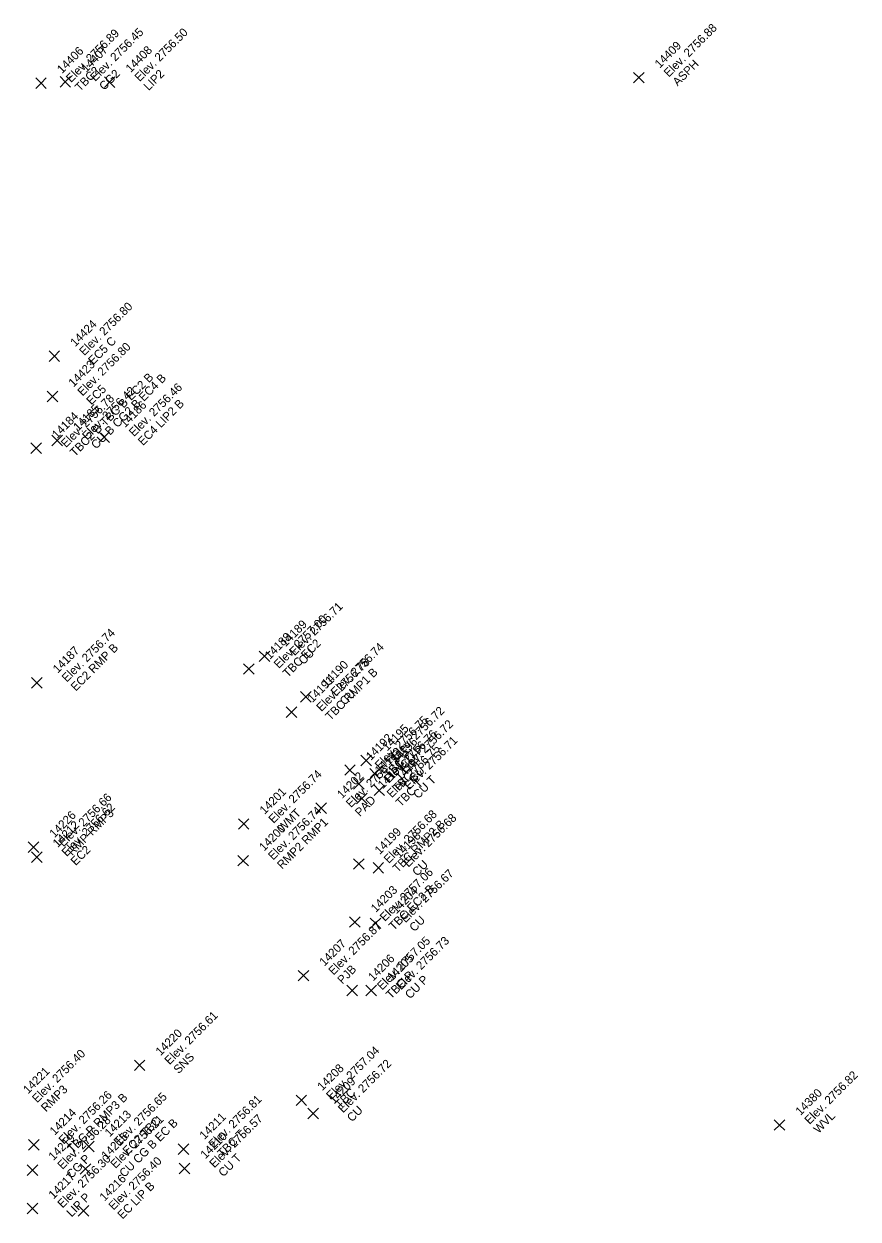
# Model space of a CAD drawing. Extents: x 2493999 to 2503109, y 700767 to 706646.
# Drawn here: x 2502335.47 to 2502359.11, y 703210.64 to 703244.51 of the extents above; entities that cross this region are included whole.
import ezdxf

# ---------------------------------------------------------------- set-up
doc = ezdxf.new("R2010")
doc.units = 0
doc.layers.add('ALG_CL_BLUE_Horiz', color=7, linetype='Continuous')
doc.layers.add('DES_SURFACE_Existing-Ground', color=7, linetype='Continuous')

msp = doc.modelspace()

# ---------------------------------------------------------------- linework, layer by layer
at = {"layer": 'ALG_CL_BLUE_Horiz'}
for points in [[(2502352.892, 703242.983), (2502352.742, 703243.133), (2502352.892, 703242.983), (2502352.742, 703242.833), (2502352.892, 703242.983), (2502353.042, 703242.833), (2502352.892, 703242.983), (2502353.042, 703243.133)], [(2502335.954, 703242.83), (2502335.804, 703242.98), (2502335.954, 703242.83), (2502335.804, 703242.68), (2502335.954, 703242.83), (2502336.104, 703242.68), (2502335.954, 703242.83), (2502336.104, 703242.98)], [(2502336.642, 703242.861), (2502336.492, 703243.011), (2502336.642, 703242.861), (2502336.492, 703242.711), (2502336.642, 703242.861), (2502336.792, 703242.711), (2502336.642, 703242.861), (2502336.792, 703243.011)], [(2502337.899, 703242.855), (2502337.749, 703243.005), (2502337.899, 703242.855), (2502337.749, 703242.705), (2502337.899, 703242.855), (2502338.049, 703242.705), (2502337.899, 703242.855), (2502338.049, 703243.005)], [(2502336.332, 703235.088), (2502336.182, 703235.238), (2502336.332, 703235.088), (2502336.182, 703234.938), (2502336.332, 703235.088), (2502336.482, 703234.938), (2502336.332, 703235.088), (2502336.482, 703235.238)], [(2502336.279, 703233.947), (2502336.129, 703234.097), (2502336.279, 703233.947), (2502336.129, 703233.797), (2502336.279, 703233.947), (2502336.429, 703233.797), (2502336.279, 703233.947), (2502336.429, 703234.097)], [(2502337.74, 703232.796), (2502337.59, 703232.946), (2502337.74, 703232.796), (2502337.59, 703232.646), (2502337.74, 703232.796), (2502337.89, 703232.646), (2502337.74, 703232.796), (2502337.89, 703232.946)], [(2502335.813, 703232.483), (2502335.663, 703232.633), (2502335.813, 703232.483), (2502335.663, 703232.333), (2502335.813, 703232.483), (2502335.963, 703232.333), (2502335.813, 703232.483), (2502335.963, 703232.633)], [(2502336.413, 703232.698), (2502336.263, 703232.848), (2502336.413, 703232.698), (2502336.263, 703232.548), (2502336.413, 703232.698), (2502336.563, 703232.548), (2502336.413, 703232.698), (2502336.563, 703232.848)], [(2502342.288, 703226.587), (2502342.138, 703226.737), (2502342.288, 703226.587), (2502342.138, 703226.437), (2502342.288, 703226.587), (2502342.438, 703226.437), (2502342.288, 703226.587), (2502342.438, 703226.737)], [(2502341.843, 703226.228), (2502341.693, 703226.378), (2502341.843, 703226.228), (2502341.693, 703226.078), (2502341.843, 703226.228), (2502341.993, 703226.078), (2502341.843, 703226.228), (2502341.993, 703226.378)], [(2502335.836, 703225.838), (2502335.686, 703225.988), (2502335.836, 703225.838), (2502335.686, 703225.688), (2502335.836, 703225.838), (2502335.986, 703225.688), (2502335.836, 703225.838), (2502335.986, 703225.988)], [(2502343.457, 703225.438), (2502343.307, 703225.588), (2502343.457, 703225.438), (2502343.307, 703225.288), (2502343.457, 703225.438), (2502343.607, 703225.288), (2502343.457, 703225.438), (2502343.607, 703225.588)], [(2502343.052, 703225.005), (2502342.902, 703225.155), (2502343.052, 703225.005), (2502342.902, 703224.855), (2502343.052, 703225.005), (2502343.202, 703224.855), (2502343.052, 703225.005), (2502343.202, 703225.155)], [(2502345.17, 703223.633), (2502345.02, 703223.783), (2502345.17, 703223.633), (2502345.02, 703223.483), (2502345.17, 703223.633), (2502345.32, 703223.483), (2502345.17, 703223.633), (2502345.32, 703223.783)], [(2502344.709, 703223.365), (2502344.559, 703223.515), (2502344.709, 703223.365), (2502344.559, 703223.215), (2502344.709, 703223.365), (2502344.859, 703223.215), (2502344.709, 703223.365), (2502344.859, 703223.515)], [(2502344.959, 703222.972), (2502344.809, 703223.122), (2502344.959, 703222.972), (2502344.809, 703222.822), (2502344.959, 703222.972), (2502345.109, 703222.822), (2502344.959, 703222.972), (2502345.109, 703223.122)], [(2502345.417, 703223.256), (2502345.267, 703223.406), (2502345.417, 703223.256), (2502345.267, 703223.106), (2502345.417, 703223.256), (2502345.567, 703223.106), (2502345.417, 703223.256), (2502345.567, 703223.406)], [(2502345.54, 703222.789), (2502345.39, 703222.939), (2502345.54, 703222.789), (2502345.39, 703222.639), (2502345.54, 703222.789), (2502345.69, 703222.639), (2502345.54, 703222.789), (2502345.69, 703222.939)], [(2502343.891, 703222.282), (2502343.741, 703222.432), (2502343.891, 703222.282), (2502343.741, 703222.132), (2502343.891, 703222.282), (2502344.041, 703222.132), (2502343.891, 703222.282), (2502344.041, 703222.432)], [(2502345.046, 703222.559), (2502344.896, 703222.709), (2502345.046, 703222.559), (2502344.896, 703222.409), (2502345.046, 703222.559), (2502345.196, 703222.409), (2502345.046, 703222.559), (2502345.196, 703222.709)], [(2502341.697, 703221.836), (2502341.547, 703221.986), (2502341.697, 703221.836), (2502341.547, 703221.686), (2502341.697, 703221.836), (2502341.847, 703221.686), (2502341.697, 703221.836), (2502341.847, 703221.986)], [(2502335.74, 703221.176), (2502335.59, 703221.326), (2502335.74, 703221.176), (2502335.59, 703221.026), (2502335.74, 703221.176), (2502335.89, 703221.026), (2502335.74, 703221.176), (2502335.89, 703221.326)], [(2502335.834, 703220.896), (2502335.684, 703221.046), (2502335.834, 703220.896), (2502335.684, 703220.746), (2502335.834, 703220.896), (2502335.984, 703220.746), (2502335.834, 703220.896), (2502335.984, 703221.046)], [(2502341.682, 703220.796), (2502341.532, 703220.946), (2502341.682, 703220.796), (2502341.532, 703220.646), (2502341.682, 703220.796), (2502341.832, 703220.646), (2502341.682, 703220.796), (2502341.832, 703220.946)], [(2502344.958, 703220.702), (2502344.808, 703220.852), (2502344.958, 703220.702), (2502344.808, 703220.552), (2502344.958, 703220.702), (2502345.108, 703220.552), (2502344.958, 703220.702), (2502345.108, 703220.852)], [(2502345.513, 703220.595), (2502345.363, 703220.745), (2502345.513, 703220.595), (2502345.363, 703220.445), (2502345.513, 703220.595), (2502345.663, 703220.445), (2502345.513, 703220.595), (2502345.663, 703220.745)], [(2502344.849, 703219.058), (2502344.699, 703219.208), (2502344.849, 703219.058), (2502344.699, 703218.908), (2502344.849, 703219.058), (2502344.999, 703218.908), (2502344.849, 703219.058), (2502344.999, 703219.208)], [(2502345.431, 703219.021), (2502345.281, 703219.171), (2502345.431, 703219.021), (2502345.281, 703218.871), (2502345.431, 703219.021), (2502345.581, 703218.871), (2502345.431, 703219.021), (2502345.581, 703219.171)], [(2502343.39, 703217.538), (2502343.24, 703217.688), (2502343.39, 703217.538), (2502343.24, 703217.388), (2502343.39, 703217.538), (2502343.54, 703217.388), (2502343.39, 703217.538), (2502343.54, 703217.688)], [(2502344.77, 703217.115), (2502344.62, 703217.265), (2502344.77, 703217.115), (2502344.62, 703216.965), (2502344.77, 703217.115), (2502344.92, 703216.965), (2502344.77, 703217.115), (2502344.92, 703217.265)], [(2502345.308, 703217.117), (2502345.158, 703217.267), (2502345.308, 703217.117), (2502345.158, 703216.967), (2502345.308, 703217.117), (2502345.458, 703216.967), (2502345.308, 703217.117), (2502345.458, 703217.267)], [(2502338.749, 703214.998), (2502338.599, 703215.148), (2502338.749, 703214.998), (2502338.599, 703214.848), (2502338.749, 703214.998), (2502338.899, 703214.848), (2502338.749, 703214.998), (2502338.899, 703215.148)], [(2502343.331, 703214.006), (2502343.181, 703214.156), (2502343.331, 703214.006), (2502343.181, 703213.856), (2502343.331, 703214.006), (2502343.481, 703213.856), (2502343.331, 703214.006), (2502343.481, 703214.156)], [(2502343.663, 703213.633), (2502343.513, 703213.783), (2502343.663, 703213.633), (2502343.513, 703213.483), (2502343.663, 703213.633), (2502343.813, 703213.483), (2502343.663, 703213.633), (2502343.813, 703213.783)], [(2502356.883, 703213.306), (2502356.733, 703213.456), (2502356.883, 703213.306), (2502356.733, 703213.156), (2502356.883, 703213.306), (2502357.033, 703213.156), (2502356.883, 703213.306), (2502357.033, 703213.456)], [(2502335.748, 703212.744), (2502335.598, 703212.894), (2502335.748, 703212.744), (2502335.598, 703212.594), (2502335.748, 703212.744), (2502335.898, 703212.594), (2502335.748, 703212.744), (2502335.898, 703212.894)], [(2502337.306, 703212.696), (2502337.156, 703212.846), (2502337.306, 703212.696), (2502337.156, 703212.546), (2502337.306, 703212.696), (2502337.456, 703212.546), (2502337.306, 703212.696), (2502337.456, 703212.846)], [(2502339.993, 703212.624), (2502339.843, 703212.774), (2502339.993, 703212.624), (2502339.843, 703212.474), (2502339.993, 703212.624), (2502340.143, 703212.474), (2502339.993, 703212.624), (2502340.143, 703212.774)], [(2502335.714, 703212.029), (2502335.564, 703212.179), (2502335.714, 703212.029), (2502335.564, 703211.879), (2502335.714, 703212.029), (2502335.864, 703211.879), (2502335.714, 703212.029), (2502335.864, 703212.179)], [(2502337.212, 703212.06), (2502337.062, 703212.21), (2502337.212, 703212.06), (2502337.062, 703211.91), (2502337.212, 703212.06), (2502337.362, 703211.91), (2502337.212, 703212.06), (2502337.362, 703212.21)], [(2502340.019, 703212.076), (2502339.869, 703212.226), (2502340.019, 703212.076), (2502339.869, 703211.926), (2502340.019, 703212.076), (2502340.169, 703211.926), (2502340.019, 703212.076), (2502340.169, 703212.226)], [(2502335.714, 703210.938), (2502335.564, 703211.088), (2502335.714, 703210.938), (2502335.564, 703210.788), (2502335.714, 703210.938), (2502335.864, 703210.788), (2502335.714, 703210.938), (2502335.864, 703211.088)], [(2502337.16, 703210.876), (2502337.01, 703211.026), (2502337.16, 703210.876), (2502337.01, 703210.726), (2502337.16, 703210.876), (2502337.31, 703210.726), (2502337.16, 703210.876), (2502337.31, 703211.026)]]:
    msp.add_lwpolyline(points, dxfattribs=at)

# ---------------------------------------------------------------- texts
at = {"layer": 'DES_SURFACE_Existing-Ground'}
for s, p in [('Elev. 2756.88', (2502353.741, 703242.983)), ('Elev. 2756.89', (2502336.803, 703242.83)), ('Elev. 2756.45', (2502337.491, 703242.861)), ('Elev. 2756.50', (2502338.748, 703242.855)), ('14406', (2502336.548, 703243.085)), ('14407', (2502337.236, 703243.116)), ('14408', (2502338.493, 703243.11)), ('14409', (2502353.486, 703243.238)), ('ASPH', (2502353.995, 703242.728)), ('TBC2', (2502337.057, 703242.575)), ('CG2', (2502337.745, 703242.606)), ('LIP2', (2502339.002, 703242.6)), ('Elev. 2756.80', (2502337.181, 703235.088)), ('14424', (2502336.926, 703235.343)), ('EC5 C', (2502337.435, 703234.833)), ('Elev. 2756.80', (2502337.128, 703233.947)), ('14423', (2502336.873, 703234.202)), ('TBC2 B TBC B EC2 B', (2502336.916, 703232.228)), ('EC5', (2502337.382, 703233.692)), ('CU B CG2 B EC4 B', (2502337.516, 703232.443)), ('Elev. 2756.46', (2502338.589, 703232.796)), ('Elev. 2756.78', (2502336.662, 703232.483)), ('Elev. 2756.42', (2502337.262, 703232.698)), ('14185', (2502337.007, 703232.953)), ('14186', (2502338.334, 703233.051)), ('EC4 LIP2 B', (2502338.843, 703232.541)), ('14184', (2502336.407, 703232.738)), ('Elev. 2756.71', (2502343.137, 703226.587)), ('Elev. 2757.00', (2502342.692, 703226.228)), ('14189', (2502342.882, 703226.842)), ('Elev. 2756.74', (2502336.685, 703225.838)), ('14188', (2502342.437, 703226.483)), ('14187', (2502336.43, 703226.093)), ('EC2 RMP B', (2502336.939, 703225.583)), ('TBC EC2', (2502342.946, 703225.973)), ('Elev. 2756.74', (2502344.306, 703225.438)), ('CU', (2502343.391, 703226.332)), ('Elev. 2756.78', (2502343.901, 703225.005)), ('14190', (2502344.051, 703225.693)), ('TBC RMP1 B', (2502344.155, 703224.75)), ('14191', (2502343.646, 703225.26)), ('CU', (2502344.56, 703225.183)), ('Elev. 2756.72', (2502346.019, 703223.633)), ('Elev. 2756.75', (2502345.558, 703223.365)), ('14195', (2502345.764, 703223.888)), ('Elev. 2756.76', (2502345.808, 703222.972)), ('Elev. 2756.72', (2502346.266, 703223.256)), ('14192', (2502345.303, 703223.62)), ('14196', (2502346.011, 703223.511)), ('Elev. 2756.71', (2502346.389, 703222.789)), ('Elev. 2756.73', (2502344.74, 703222.282)), ('14193', (2502345.553, 703223.227)), ('TBC P', (2502345.812, 703223.11)), ('Elev. 2756.75', (2502345.895, 703222.559)), ('14197', (2502346.134, 703223.044)), ('CU P', (2502346.273, 703223.378)), ('14194', (2502345.64, 703222.814)), ('CU', (2502346.52, 703223.001)), ('Elev. 2756.74', (2502342.546, 703221.836)), ('14202', (2502344.485, 703222.537)), ('TBC', (2502346.062, 703222.717)), ('TBC T', (2502346.149, 703222.304)), ('CU T', (2502346.643, 703222.534)), ('14201', (2502342.291, 703222.091)), ('Elev. 2756.66', (2502336.589, 703221.176)), ('Elev. 2756.62', (2502336.683, 703220.896)), ('PAD', (2502344.994, 703222.027)), ('14226', (2502336.334, 703221.431)), ('RMP RMP3', (2502336.843, 703220.921)), ('Elev. 2756.74', (2502342.531, 703220.796)), ('WMT', (2502342.8, 703221.581)), ('Elev. 2756.68', (2502345.807, 703220.702)), ('Elev. 2756.68', (2502346.362, 703220.595)), ('14212', (2502336.428, 703221.151)), ('14200', (2502342.276, 703221.051)), ('RMP2 RMP1', (2502342.785, 703220.541)), ('TBC RMP2 B', (2502346.061, 703220.447)), ('14199', (2502345.552, 703220.957)), ('14198', (2502346.107, 703220.85)), ('EC2', (2502336.937, 703220.641)), ('CU', (2502346.616, 703220.34)), ('Elev. 2757.06', (2502345.698, 703219.058)), ('Elev. 2756.67', (2502346.28, 703219.021)), ('14203', (2502345.443, 703219.313)), ('TBC EC2 B', (2502345.952, 703218.803)), ('14204', (2502346.025, 703219.276)), ('Elev. 2756.87', (2502344.239, 703217.538)), ('CU', (2502346.534, 703218.766)), ('14207', (2502343.984, 703217.793)), ('Elev. 2757.05', (2502345.619, 703217.115)), ('Elev. 2756.73', (2502346.157, 703217.117)), ('14206', (2502345.364, 703217.37)), ('14205', (2502345.902, 703217.372)), ('PJB', (2502344.493, 703217.283)), ('TBC P', (2502345.873, 703216.86)), ('CU P', (2502346.411, 703216.862)), ('Elev. 2756.61', (2502339.598, 703214.998)), ('14220', (2502339.343, 703215.253)), ('Elev. 2756.40', (2502335.844, 703213.917)), ('SNS', (2502339.852, 703214.743)), ('Elev. 2757.04', (2502344.18, 703214.006)), ('14208', (2502343.925, 703214.261)), ('Elev. 2756.72', (2502344.512, 703213.633)), ('14221', (2502335.589, 703214.172)), ('14209', (2502344.257, 703213.888)), ('Elev. 2756.82', (2502357.732, 703213.306)), ('RMP3', (2502336.098, 703213.662)), ('TBC', (2502344.434, 703213.751)), ('14380', (2502357.477, 703213.561)), ('Elev. 2756.26', (2502336.597, 703212.744)), ('TBC P RMP3 B', (2502336.851, 703212.489)), ('Elev. 2756.65', (2502338.155, 703212.696)), ('Elev. 2756.81', (2502340.842, 703212.624)), ('14214', (2502336.342, 703212.999)), ('14213', (2502337.9, 703212.951)), ('14211', (2502340.587, 703212.879)), ('Elev. 2756.57', (2502340.868, 703212.076)), ('CU', (2502344.766, 703213.378)), ('WVL', (2502357.986, 703213.051)), ('Elev. 2756.28', (2502336.563, 703212.029)), ('Elev. 2756.21', (2502338.061, 703212.06)), ('CU CG B EC B', (2502338.315, 703211.805)), ('EC2 TBC', (2502338.409, 703212.441)), ('14219', (2502336.308, 703212.284)), ('14215', (2502337.806, 703212.315)), ('14210', (2502340.613, 703212.331)), ('TBC T', (2502341.096, 703212.369)), ('Elev. 2756.30', (2502336.563, 703210.938)), ('CG P', (2502336.817, 703211.774)), ('Elev. 2756.40', (2502338.009, 703210.876)), ('CU T', (2502341.122, 703211.821)), ('14217', (2502336.308, 703211.193)), ('14216', (2502337.754, 703211.131)), ('EC LIP B', (2502338.263, 703210.621)), ('LIP P', (2502336.817, 703210.683))]:
    msp.add_text(s, height=0.24, rotation=45, dxfattribs=at).set_placement(p)

doc.saveas('drawing.dxf')
